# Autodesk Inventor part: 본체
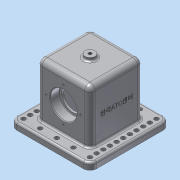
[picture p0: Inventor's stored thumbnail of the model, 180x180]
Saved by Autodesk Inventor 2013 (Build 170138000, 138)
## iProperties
Created: 2018-11
Part Number: 본체
Material: 알루미늄 6061
Document SubType Name: Modeling
Designer: dgall
Density: 1 g/cm^3
Author: dgall
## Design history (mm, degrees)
sketch "스케치1"
  geometry: L1 (0, 0)-(80, 0); L2 (80, 0)-(80, 80); L3 (80, 80)-(0, 80); L4 (0, 80)-(0, 0)
  constraints: 8 end point, 2 parallel, 2 perpendicular, 1 horizontal
  dimensions: "d0" = 80 distance of L2.end L3.end
extrude "돌출1" new body sketch "스케치1" distance "d2" = 90; taper "d3" = 0 deg
node "작업 평면1"
sketch "스케치2"
  geometry: L1 (0, 48)-(80, 48); L2 (0, 0)-(0, 90) reference; L3 (80, 0)-(80, 90) reference; L4 (80, 0)-(0, 0) reference; L5 (0, 48)-(0, 68); L6 (0, 68)-(14, 68); L7 (14, 68)-(14, 64.5); L8 (14, 64.5)-(66, 64.5); L9 (66, 64.5)-(66, 68); L10 (66, 68)-(80, 68); L11 (80, 68)-(80, 48)
  constraints: 17 end point, 5 perpendicular, 3 point on line, 1 horizontal
  dimensions: "d4" = 48 distance between parallel lines of L4 L1; "d5" = 40 diameter of L5.end L1; "d6" = 33 diameter of L8 L1; "d7" = 40 diameter of L10.end L1; "d8" = 14 distance of L9.end L10.end; "d9" = 14 distance of L5.end L6.end
revolve "회전1" sketch "스케치2" stored, may be unused: angle "d10" = 90 deg
sketch "스케치3"
  geometry: L1 (-80, 80)-(0, 80) reference; L2 (-80, 0)-(-80, 80) reference; L3 (0, 80)-(0, 0) reference; L4 (-10, 63)-(-10, 17); L5 (-70, 63)-(-70, 17); L6 (-70, 63)-(-10, 63); L7 (-70, 17)-(-10, 17); 6 further points
  constraints: 8 end point, 6 midpoint, 3 parallel, 1 horizontal alignment, 1 perpendicular, 1 vertical alignment
  dimensions: "d91" = 46 distance of L5.start L5.end; "d93" = 60 distance of L5.start L4.start
extrude "돌출2" cut sketch "스케치3" distance "d13" = 80; taper "d14" = 0 deg
node "작업 평면2"
sketch "스케치4"
  geometry: L1 (0, 80)-(0, 0) reference; L2 (80, 80)-(0, 80) reference; C1 r 7.5 at (40, 40); 2 further points
  constraints: 2 midpoint, 1 centre point, 1 horizontal alignment, 1 vertical alignment
  dimensions: "d16" = 15 diameter of C1
extrude "돌출3" join sketch "스케치4" stored distance "d18" = 80; taper "d19" = 0 deg
sketch "스케치5" dims "d20" = 52
  geometry: C1 r 20 at (40, 48) reference; 2 further points
  constraints: 2 vertical alignment, 1 coincident, 2 other
hole "구멍1" sketch "스케치5" at (40, 74) diameter "d21" = 3.242; stored, may be unused: countersink angle "d25" = 90 deg, drill point angle "d27" = 118 deg; dims "d22" = 8, "d23" = 4, "d24" = 2, "d26" = 10
sketch "스케치6" dims "d31" = 52
  geometry: C1 r 20 at (40, -48) reference; 2 further points
  constraints: 2 vertical alignment, 1 coincident, 2 other
hole "구멍2" sketch "스케치6" at (40, -22) diameter "d32" = 3.242; stored, may be unused: countersink angle "d36" = 90 deg, drill point angle "d38" = 118 deg; dims "d33" = 8, "d34" = 4, "d35" = 2, "d37" = 10
sketch "스케치7"
  geometry: C1 r 7.5 at (0, 0) reference; 2 further points
  constraints: 1 coincident
hole "구멍3" sketch "스케치7" at (0, 0) diameter "d42" = 4.917; stored, may be unused: countersink angle "d46" = 90 deg, drill point angle "d48" = 118 deg; dims "d43" = 8, "d44" = 4, "d45" = 2, "d47" = 10
sketch "스케치8"
  geometry: L1 (0, 0)-(-80, 0) reference; L2 (0, 80)-(0, 0) reference; L3 (-80, 80)-(0, 80) reference; L4 (-80, 0)-(-80, 80) reference; L5 (-100, 100)-(20, 100); L6 (20, 100)-(20, -20); L7 (20, -20)-(-100, -20); L8 (-100, -20)-(-100, 100); L9 (-70, 17)-(-70, 63) reference; L10 (-70, 63)-(-10, 63) reference; 4 further points
  constraints: 8 end point, 4 midpoint, 2 parallel, 2 perpendicular, 1 horizontal, 1 horizontal alignment, 1 vertical alignment
  dimensions: "d49" = 120 distance of L5.start L5.end
extrude "돌출4" join sketch "스케치8" distance "d51" = 10; taper "d52" = 0 deg
fillet "모깎기1" dims "d53" = 0.6
fillet "모깎기2" dims "d54" = 3
fillet "모깎기3" dims "d55" = 3
fillet "모깎기4" dims "d56" = 8
fillet "모깎기5" dims "d57" = 8
fillet "모깎기6" dims "d58" = 3
chamfer "모따기1" distance "d59" = 1; stored, may be unused: second distance "d60" = 2, angle "d61" = 45 deg
fillet "모깎기7" dims "d62" = 10
fillet "모깎기8" dims "d63" = 3
sketch "스케치9"
  geometry: L1 (90, -17)-(-10, -17) reference; L2 (-17, -10)-(-17, 90) reference; C1 r 3.3 at (-10, -10); C2 r 3.3 at (-10, 0); C3 r 3.3 at (-10, 10); C4 r 3.3 at (-10, 20); C5 r 3.3 at (-10, 30); C6 r 3.3 at (-10, 40); C7 r 3.3 at (-10, 50); C8 r 3.3 at (-10, 60); C9 r 3.3 at (-10, 70); C10 r 3.3 at (-10, 80); C11 r 3.3 at (-10, 90); C12 r 3.3 at (90, -10); C13 r 3.3 at (90, 0); C14 r 3.3 at (90, 10); C15 r 3.3 at (90, 20); C16 r 3.3 at (90, 30); C17 r 3.3 at (90, 40); C18 r 3.3 at (90, 50); C19 r 3.3 at (90, 60); C20 r 3.3 at (90, 70); C21 r 3.3 at (90, 80); C22 r 3.3 at (90, 90); C23 r 3.3 at (15, -10); C24 r 3.3 at (40, -10); C25 r 3.3 at (65, -10); C26 r 3.3 at (15, 90); C27 r 3.3 at (40, 90); C28 r 3.3 at (65, 90); A1 r 7 centre (-10, -10) between (-17, -10) and (-10, -17) reference; A2 r 7 centre (90, -10) between (90, -17) and (97, -10) reference; 1 further point
  constraints: 28 centre point, 3 horizontal alignment, 2 horizontal, 2 vertical, 1 coincident, 52 other
  dimensions: "d64" = 6.6 diameter of C1; "d68" = 10 distance of C1.centre C2.centre; "d71" = 100 distance of C1.centre C12.centre; "d74" = 6.6 diameter of C23; "d75" = 25 distance of C23.centre A1.centre; "d78" = 25 distance of C23.centre C24.centre; "d81" = 100 distance of C23.centre C26.centre
extrude "돌출5" cut sketch "스케치9" stored distance "d84" = 10; taper "d85" = 0 deg
node "작업 평면3"
sketch "스케치10"
  geometry: L1 (-85, 24.5)-(-85, 39.5) reference; L2 (10, 92)-(10, 82) reference; 3 further points
  constraints: 1 horizontal alignment, 1 midpoint, 1 other
  dimensions: "d87" = 48 horizontal distance of point (-38, 32) L2.start
feature "엠보싱1" sketch "스케치10" dims "d0" = 80, "d7" = 40, "d88" = 0.5, "d89" = 0
fillet "모깎기9" dims "d90" = 3
node "솔리드1"
pattern_circular "원형 패턴1" dims angle "d29" = 360 deg
pattern_circular "원형 패턴2" dims angle "d40" = 360 deg
other parameters: "d15" = 5, "d86" = 20.75
